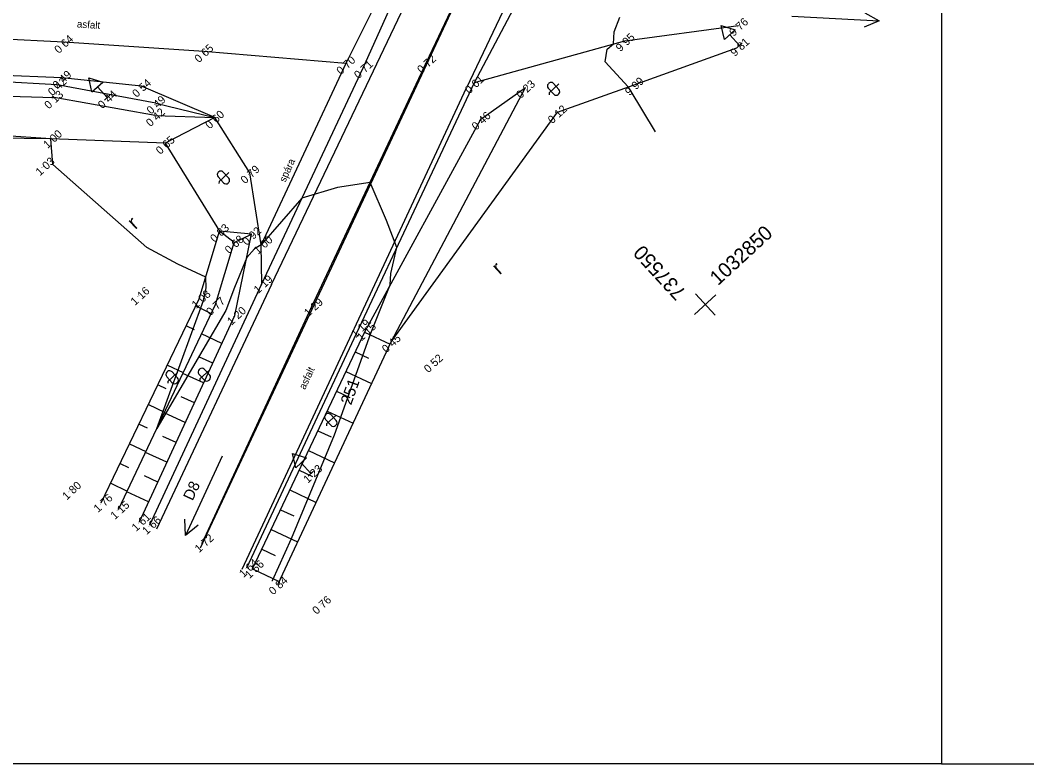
# Model space of a CAD drawing. Extents: x -740053 to -737481, y -1033516 to -1032488.
# Drawn here: x -737650.4 to -737581.2, y -1032955.3 to -1032904.2 of the extents above; entities that cross this region are included whole.
import ezdxf

# ---------------------------------------------------------------- set-up
doc = ezdxf.new("R2010")
doc.units = 0
for name, color, linetype in [('bod-oznac', 7, 'Continuous'), ('bod-vyska', 7, 'Continuous'), ('bod-vyska100', 7, 'Continuous'), ('Contours', 7, 'Continuous'), ('Contours highlighted', 7, 'Continuous'), ('Contours text', 7, 'Continuous'), ('ctv-sit', 7, 'Continuous'), ('dopr-zariz', 7, 'Continuous'), ('nazvy-bud-povr', 7, 'Continuous'), ('osa-komunikace', 7, 'Continuous'), ('Predmety bez rozlišeni', 7, 'Continuous'), ('promika-formát', 7, 'Continuous'), ('rozhraní kultůr', 7, 'Continuous'), ('silnice', 7, 'Continuous'), ('silnice-spára', 7, 'Continuous'), ('Technické šrafy', 7, 'Continuous'), ('Terenni-hrana', 7, 'Continuous'), ('vodorovne znašení', 7, 'Continuous'), ('Znacky-kultury', 7, 'Continuous')]:
    doc.layers.add(name, color=color, linetype=linetype)

# ---------------------------------------------------------------- blocks, each defined once
blk = doc.blocks.new('d_znacka')
for p, q in [((-1, 2), (0, 3.73)), ((0, 3.73), (1, 2)), ((-1, 2), (1, 2)), ((0, 0), (0, 2)), ((-0.5, 0), (0.5, 0))]:
    blk.add_line(p, q)
blk = doc.blocks.new('vo_votok')
for p, q in [((-3, 0), (3, 0)), ((2, 0.5), (3, 0)), ((3, 0), (2, -0.5))]:
    blk.add_line(p, q)
blk = doc.blocks.new('p_orna')
blk.add_text('r', height=2).set_placement((0, 0))
blk = doc.blocks.new('p_neplod')
for p, q in [((-0.82, 0), (-0.99, -0.18)), ((1, 0), (-0.82, 0)), ((-0.49, 0.56), (-0.49, -0.55)), ((0.05, 1.01), (-0.04, 1.01)), ((0.5, -0.55), (0.5, 0.56)), ((-0.04, -1), (0.05, -1))]:
    blk.add_line(p, q)
for centre, start, end in [((-0.04, 0.56), 90, 180), ((0.05, 0.56), 0, 90), ((-0.04, -0.55), 180, 270), ((0.05, -0.55), 270, 0)]:
    blk.add_arc(centre, 0.45, start, end)
blk = doc.blocks.new('POINT_DISPLAY')
blk.add_line((0, 0), (0, 0))
blk = doc.blocks.new('ctvsit')
for p, q in [((0, -2), (0, 2)), ((2, 0), (-2, 0))]:
    blk.add_line(p, q)

msp = doc.modelspace()

# ---------------------------------------------------------------- linework, layer by layer
at = {"layer": 'Contours'}
msp.add_lwpolyline([(-737633.096, -1032942.675), (-737633.055, -1032942.669), (-737631.741, -1032939.791), (-737628.784, -1032932.66), (-737626.302, -1032925.695), (-737624.954, -1032922.373), (-737624.915, -1032921.584), (-737624.501, -1032919.8), (-737625.226, -1032917.943), (-737626.348, -1032915.337), (-737628.584, -1032915.671), (-737631.025, -1032916.415), (-737633.817, -1032919.611), (-737634.28, -1032919.901), (-737634.817, -1032920.492), (-737635.657, -1032922.55), (-737636.26, -1032924.126), (-737640.999, -1032932.239), (-737637.792, -1032923.436), (-737637.599, -1032922.563), (-737637.635, -1032921.848), (-737639.553, -1032920.954), (-737641.671, -1032919.812), (-737648.137, -1032914.092), (-737648.281, -1032912.342), (-737669.875, -1032910.89)], dxfattribs=at)
at = {"layer": 'Contours highlighted'}
msp.add_lwpolyline([(-737606.729, -1032911.86), (-737608.469, -1032908.981), (-737608.613, -1032908.767), (-737610.2, -1032907.045), (-737610.058, -1032906.175), (-737609.622, -1032905.82), (-737609.57, -1032905.001), (-737609.198, -1032903.983)], dxfattribs=at)
at = {"layer": 'osa-komunikace'}
for p, q in [((-737622.475, -1032907.08), (-737613.983, -1032889.1)), ((-737647.386, -1032905.706), (-737669.401, -1032904.63)), ((-737637.759, -1032906.338), (-737647.386, -1032905.706)), ((-737628.02, -1032907.165), (-737637.759, -1032906.338)), ((-737630.359, -1032923.889), (-737622.475, -1032907.08)), ((-737637.871, -1032940.099), (-737630.359, -1032923.889))]:
    msp.add_line(p, q, dxfattribs=at)
at = {"layer": 'Predmety bez rozlišeni'}
msp.add_line((-737587.097, -1032955.262), (-737692.097, -1032955.262), dxfattribs=at)
at = {"layer": 'promika-formát'}
msp.add_lwpolyline([(-737587.097, -1032955.262), (-737482.097, -1032955.262), (-737482.097, -1032806.762), (-737587.097, -1032806.762)], close=True, dxfattribs=at)
at = {"layer": 'rozhraní kultůr'}
for p, q in [((-737608.209, -1032908.622), (-737601.145, -1032906.095)), ((-737613.469, -1032910.51), (-737608.209, -1032908.622)), ((-737624.897, -1032926.271), (-737613.469, -1032910.51)), ((-737640.417, -1032912.638), (-737636.694, -1032918.683))]:
    msp.add_line(p, q, dxfattribs=at)
at = {"layer": 'silnice'}
for p, q in [((-737626.809, -1032907.453), (-737623.028, -1032899.031)), ((-737619.179, -1032908.479), (-737614.982, -1032900.559)), ((-737608.839, -1032905.602), (-737601.045, -1032904.55)), ((-737619.179, -1032908.479), (-737608.839, -1032905.602)), ((-737647.525, -1032908.156), (-737669.7, -1032907.187)), ((-737633.788, -1032922.287), (-737626.809, -1032907.453)), ((-737642.05, -1032908.733), (-737647.525, -1032908.156)), ((-737637.016, -1032910.884), (-737642.05, -1032908.733)), ((-737627.093, -1032925.315), (-737619.179, -1032908.479)), ((-737634.6, -1032914.666), (-737637.016, -1032910.884)), ((-737633.817, -1032919.611), (-737634.6, -1032914.666)), ((-737633.788, -1032922.287), (-737633.817, -1032919.611)), ((-737641.471, -1032938.857), (-737633.788, -1032922.287)), ((-737634.815, -1032941.799), (-737627.093, -1032925.315))]:
    msp.add_line(p, q, dxfattribs=at)
at = {"layer": 'silnice-spára'}
for p, q in [((-737624.96, -1032901.038), (-737628.02, -1032907.165)), ((-737628.02, -1032907.165), (-737633.817, -1032919.611))]:
    msp.add_line(p, q, dxfattribs=at)
at = {"layer": 'Technické šrafy'}
for p, q in [((-737638.31, -1032923.819), (-737637.257, -1032924.325)), ((-737638.96, -1032925.171), (-737638.429, -1032925.426)), ((-737636.523, -1032926.383), (-737637.924, -1032925.735)), ((-737626.718, -1032925.608), (-737624.973, -1032926.433)), ((-737627.359, -1032926.964), (-737626.455, -1032927.391)), ((-737637.152, -1032927.745), (-737638.06, -1032927.325)), ((-737640.26, -1032927.874), (-737639.181, -1032928.393)), ((-737628.001, -1032928.32), (-737626.243, -1032929.151)), ((-737637.782, -1032929.106), (-737639.206, -1032928.448)), ((-737640.91, -1032929.226), (-737640.366, -1032929.488)), ((-737628.642, -1032929.676), (-737627.738, -1032930.103)), ((-737638.412, -1032930.468), (-737639.32, -1032930.048)), ((-737641.56, -1032930.578), (-737640.463, -1032931.106)), ((-737629.283, -1032931.032), (-737627.513, -1032931.869)), ((-737639.042, -1032931.829), (-737640.489, -1032931.16)), ((-737642.211, -1032931.93), (-737641.657, -1032932.196)), ((-737629.925, -1032932.387), (-737629.021, -1032932.815)), ((-737639.671, -1032933.19), (-737640.579, -1032932.771)), ((-737642.861, -1032933.281), (-737641.746, -1032933.818)), ((-737640.301, -1032934.552), (-737641.771, -1032933.872)), ((-737630.566, -1032933.743), (-737628.784, -1032934.587)), ((-737643.511, -1032934.633), (-737642.949, -1032934.903)), ((-737631.208, -1032935.099), (-737630.304, -1032935.527)), ((-737640.931, -1032935.913), (-737641.839, -1032935.493)), ((-737644.161, -1032935.985), (-737643.028, -1032936.53)), ((-737641.561, -1032937.275), (-737643.054, -1032936.584)), ((-737631.849, -1032936.455), (-737630.054, -1032937.304)), ((-737632.49, -1032937.811), (-737631.586, -1032938.239)), ((-737633.132, -1032939.167), (-737631.324, -1032940.022)), ((-737633.773, -1032940.523), (-737632.869, -1032940.951)), ((-737634.415, -1032941.879), (-737632.595, -1032942.74))]:
    msp.add_line(p, q, dxfattribs=at)
at = {"layer": 'Terenni-hrana'}
for p, q in [((-737647.842, -1032908.624), (-737669.796, -1032907.466)), ((-737669.684, -1032908.83), (-737648.055, -1032909.499)), ((-737641.058, -1032909.886), (-737647.842, -1032908.624)), ((-737624.897, -1032926.271), (-737615.669, -1032908.81)), ((-737618.726, -1032910.982), (-737615.669, -1032908.81)), ((-737641.101, -1032910.741), (-737648.055, -1032909.499)), ((-737641.058, -1032909.886), (-737637.016, -1032910.884)), ((-737641.101, -1032910.741), (-737637.016, -1032910.884)), ((-737637.016, -1032910.884), (-737640.417, -1032912.638)), ((-737626.685, -1032925.537), (-737618.726, -1032910.982)), ((-737648.281, -1032912.342), (-737669.982, -1032912.051)), ((-737640.417, -1032912.638), (-737648.281, -1032912.342)), ((-737638.079, -1032923.338), (-737636.694, -1032918.683)), ((-737634.487, -1032918.896), (-737636.694, -1032918.683)), ((-737635.679, -1032919.462), (-737634.487, -1032918.896)), ((-737635.643, -1032924.481), (-737634.487, -1032918.896)), ((-737636.969, -1032923.717), (-737635.679, -1032919.462)), ((-737644.811, -1032937.337), (-737638.079, -1032923.338)), ((-737643.627, -1032937.797), (-737636.969, -1032923.717)), ((-737642.191, -1032938.636), (-737635.643, -1032924.481)), ((-737634.415, -1032941.879), (-737626.685, -1032925.537)), ((-737632.667, -1032942.894), (-737624.897, -1032926.271))]:
    msp.add_line(p, q, dxfattribs=at)
msp.add_lwpolyline([(-737635.679, -1032919.462), (-737636.694, -1032918.683)], dxfattribs=at)
at = {"layer": 'vodorovne znašení'}
for p, q in [((-737606.86, -1032873.834), (-737638.008, -1032940.454)), ((-737611.231, -1032890.949), (-737619.728, -1032908.835)), ((-737633.121, -1032922.339), (-737621.881, -1032898.799)), ((-737635.142, -1032941.881), (-737619.728, -1032908.835)), ((-737633.121, -1032922.339), (-737641.021, -1032939.141))]:
    msp.add_line(p, q, dxfattribs=at)

# ---------------------------------------------------------------- block references
at = {"layer": 'bod-oznac', "rotation": 42.589429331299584}
for p in [(-737601.045, -1032904.55), (-737647.386, -1032905.706), (-737608.839, -1032905.602), (-737600.961, -1032905.926), (-737637.759, -1032906.338), (-737628.02, -1032907.165), (-737626.809, -1032907.453), (-737622.475, -1032907.08), (-737647.525, -1032908.156), (-737647.842, -1032908.624), (-737642.05, -1032908.733), (-737619.179, -1032908.479), (-737615.669, -1032908.81), (-737608.209, -1032908.622), (-737648.055, -1032909.499), (-737644.404, -1032909.512), (-737641.058, -1032909.886), (-737641.101, -1032910.741), (-737637.016, -1032910.884), (-737618.726, -1032910.982), (-737613.469, -1032910.51), (-737648.281, -1032912.342), (-737640.417, -1032912.638), (-737648.799, -1032914.217), (-737634.6, -1032914.666), (-737636.694, -1032918.683), (-737634.487, -1032918.896), (-737635.679, -1032919.462), (-737633.817, -1032919.611), (-737633.788, -1032922.287), (-737642.244, -1032923.092), (-737638.079, -1032923.338), (-737636.969, -1032923.717), (-737630.359, -1032923.889), (-737635.643, -1032924.481), (-737627.093, -1032925.315), (-737626.685, -1032925.537), (-737624.897, -1032926.271), (-737622.01, -1032927.638), (-737630.409, -1032935.331), (-737646.969, -1032936.481), (-737644.811, -1032937.337), (-737643.627, -1032937.797), (-737642.191, -1032938.636), (-737641.471, -1032938.857), (-737637.871, -1032940.099), (-737634.815, -1032941.799), (-737634.415, -1032941.879), (-737632.667, -1032942.894), (-737629.68, -1032944.237)]:
    msp.add_blockref('POINT_DISPLAY', p, dxfattribs=at)
at = {"layer": 'ctv-sit', "xscale": 0.49999999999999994, "yscale": 0.49999999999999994, "rotation": -137.41057066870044}
msp.add_blockref('ctvsit', (-737603.324, -1032923.718), dxfattribs=at)
at = {"layer": 'dopr-zariz', "xscale": 0.4999999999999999, "yscale": 0.49999999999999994, "rotation": 42.58942933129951}
for p in [(-737600.961, -1032905.926), (-737644.404, -1032909.512), (-737630.409, -1032935.331)]:
    msp.add_blockref('d_znacka', p, dxfattribs=at)
at = {"layer": 'nazvy-bud-povr'}
for p, rotation in [((-737594.377, -1032904.074), -2.946666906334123), ((-737637.764, -1032936.857), -114.97611286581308)]:
    msp.add_blockref('vo_votok', p, dxfattribs=dict(at, rotation=rotation))
at = {"layer": 'Znacky-kultury', "xscale": 0.49999999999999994, "yscale": 0.49999999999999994, "rotation": 42.589429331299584}
for name, p in [('p_neplod', (-737613.738, -1032908.909)), ('p_neplod', (-737636.421, -1032914.997)), ('p_orna', (-737642.476, -1032918.612)), ('p_orna', (-737617.445, -1032921.717)), ('p_neplod', (-737639.946, -1032928.716)), ('p_neplod', (-737637.729, -1032928.537)), ('p_neplod', (-737629.044, -1032931.643))]:
    msp.add_blockref(name, p, dxfattribs=at)

# ---------------------------------------------------------------- texts
at = {"layer": 'bod-vyska'}
for s, p in [('9 76', (-737601.368, -1032905.345)), ('0 64', (-737647.729, -1032906.519)), ('9 95', (-737609.162, -1032906.397)), ('9 81', (-737601.284, -1032906.721)), ('0 65', (-737638.102, -1032907.15)), ('0 70', (-737628.353, -1032907.969)), ('0 72', (-737622.808, -1032907.884)), ('0 71', (-737627.142, -1032908.257)), ('0 42', (-737648.174, -1032909.428)), ('0 49', (-737647.857, -1032908.96)), ('0 54', (-737642.383, -1032909.537)), ('0 61', (-737619.522, -1032909.291)), ('9 99', (-737608.532, -1032909.417)), ('0 23', (-737616.002, -1032909.614)), ('0 13', (-737648.417, -1032910.33)), ('0 44', (-737644.737, -1032910.315)), ('0 49', (-737641.391, -1032910.69)), ('0 42', (-737641.434, -1032911.544)), ('0 12', (-737613.83, -1032911.34)), ('0 60', (-737637.359, -1032911.697)), ('0 46', (-737619.058, -1032911.786)), ('1 00', (-737648.498, -1032913.04)), ('0 65', (-737640.759, -1032913.451)), ('1 03', (-737649.016, -1032914.915)), ('0 79', (-737634.932, -1032915.47)), ('0 83', (-737637.026, -1032919.487)), ('0 92', (-737634.82, -1032919.7)), ('0 68', (-737636.021, -1032920.274)), ('1 00', (-737634.034, -1032920.308)), ('1 19', (-737634.034, -1032923.011)), ('1 16', (-737642.49, -1032923.816)), ('1 08', (-737638.296, -1032924.036)), ('0 77', (-737637.302, -1032924.521)), ('1 29', (-737630.576, -1032924.587)), ('1 20', (-737635.86, -1032925.178)), ('1 19', (-737627.339, -1032926.039)), ('1 15', (-737626.931, -1032926.262)), ('0 45', (-737625.229, -1032927.075)), ('0 52', (-737622.343, -1032928.442)), ('1 23', (-737630.626, -1032936.029)), ('1 80', (-737647.186, -1032937.179)), ('1 76', (-737645.028, -1032938.034)), ('1 15', (-737643.873, -1032938.521)), ('1 61', (-737642.417, -1032939.342)), ('1 66', (-737641.698, -1032939.564)), ('1 72', (-737638.088, -1032940.796)), ('1 64', (-737635.041, -1032942.505)), ('1 56', (-737634.632, -1032942.577)), ('0 84', (-737632.999, -1032943.698)), ('0 76', (-737630.013, -1032945.041))]:
    msp.add_text(s, height=0.55, rotation=42.58943, dxfattribs=at).set_placement(p)
at = {"layer": 'bod-vyska100'}
for s, p in [('249 76', (-737601.144, -1032904.686)), ('250 64', (-737647.487, -1032905.844)), ('249 95', (-737608.938, -1032905.738)), ('249 81', (-737601.061, -1032906.063)), ('250 65', (-737637.861, -1032906.476)), ('250 70', (-737628.121, -1032907.303)), ('250 71', (-737626.909, -1032907.591)), ('250 72', (-737622.576, -1032907.218)), ('250 49', (-737647.625, -1032908.293)), ('250 42', (-737647.942, -1032908.761)), ('250 54', (-737642.15, -1032908.871)), ('250 61', (-737619.281, -1032908.617)), ('250 23', (-737615.769, -1032908.948)), ('249 99', (-737608.308, -1032908.759)), ('250 13', (-737648.158, -1032909.639)), ('250 44', (-737644.504, -1032909.649)), ('250 49', (-737641.158, -1032910.024)), ('250 42', (-737641.202, -1032910.878)), ('250 60', (-737637.118, -1032911.023)), ('250 46', (-737618.826, -1032911.119)), ('250 12', (-737613.572, -1032910.65)), ('251 00', (-737648.376, -1032912.475)), ('250 65', (-737640.518, -1032912.776)), ('251 03', (-737648.894, -1032914.35)), ('250 79', (-737634.7, -1032914.804)), ('250 83', (-737636.794, -1032918.82)), ('250 92', (-737634.588, -1032919.034)), ('250 68', (-737635.78, -1032919.6)), ('251 00', (-737633.912, -1032919.743)), ('251 19', (-737633.886, -1032922.422)), ('251 16', (-737642.342, -1032923.227)), ('251 08', (-737638.174, -1032923.471)), ('250 77', (-737637.07, -1032923.855)), ('251 29', (-737630.454, -1032924.022)), ('251 20', (-737635.738, -1032924.614)), ('251 19', (-737627.191, -1032925.45)), ('251 15', (-737626.782, -1032925.673)), ('250 45', (-737624.997, -1032926.408)), ('250 52', (-737622.11, -1032927.776)), ('251 23', (-737630.504, -1032935.464)), ('251 80', (-737647.064, -1032936.614)), ('251 76', (-737644.906, -1032937.469)), ('251 15', (-737643.725, -1032937.932)), ('251 61', (-737642.287, -1032938.769)), ('251 66', (-737641.567, -1032938.991)), ('251 72', (-737637.966, -1032940.232)), ('251 64', (-737634.911, -1032941.932)), ('251 56', (-737634.51, -1032942.012)), ('250 84', (-737632.767, -1032943.032)), ('250 76', (-737629.78, -1032944.375))]:
    msp.add_text(s, height=0.05, rotation=42.58943, dxfattribs=at).set_placement(p)
at = {"layer": 'Contours text'}
msp.add_text('251', height=0.8, rotation=70.38541, dxfattribs=at).set_placement((-737627.65, -1032930.669))
at = {"layer": 'ctv-sit'}
for s, rotation, p in [('1032850', 42.58943, (-737602.445, -1032922.458)), ('737550', 132.58943, (-737604.584, -1032922.84))]:
    msp.add_text(s, height=1, rotation=rotation, dxfattribs=at).set_placement(p)
at = {"layer": 'nazvy-bud-povr'}
for s, height, rotation, p in [('asfalt', 0.5, 355.9689, (-737646.496, -1032904.685)), ('asfalt', 0.5, 65.0387, (-737630.81, -1032929.601)), ('D8', 0.75, 64.99062, (-737638.542, -1032937.238))]:
    msp.add_text(s, height=height, rotation=rotation, dxfattribs=at).set_placement(p)
at = {"layer": 'silnice-spára'}
msp.add_text('spára', height=0.5, rotation=65.63277, dxfattribs=at).set_placement((-737632.17, -1032915.365))

doc.saveas('drawing.dxf')
